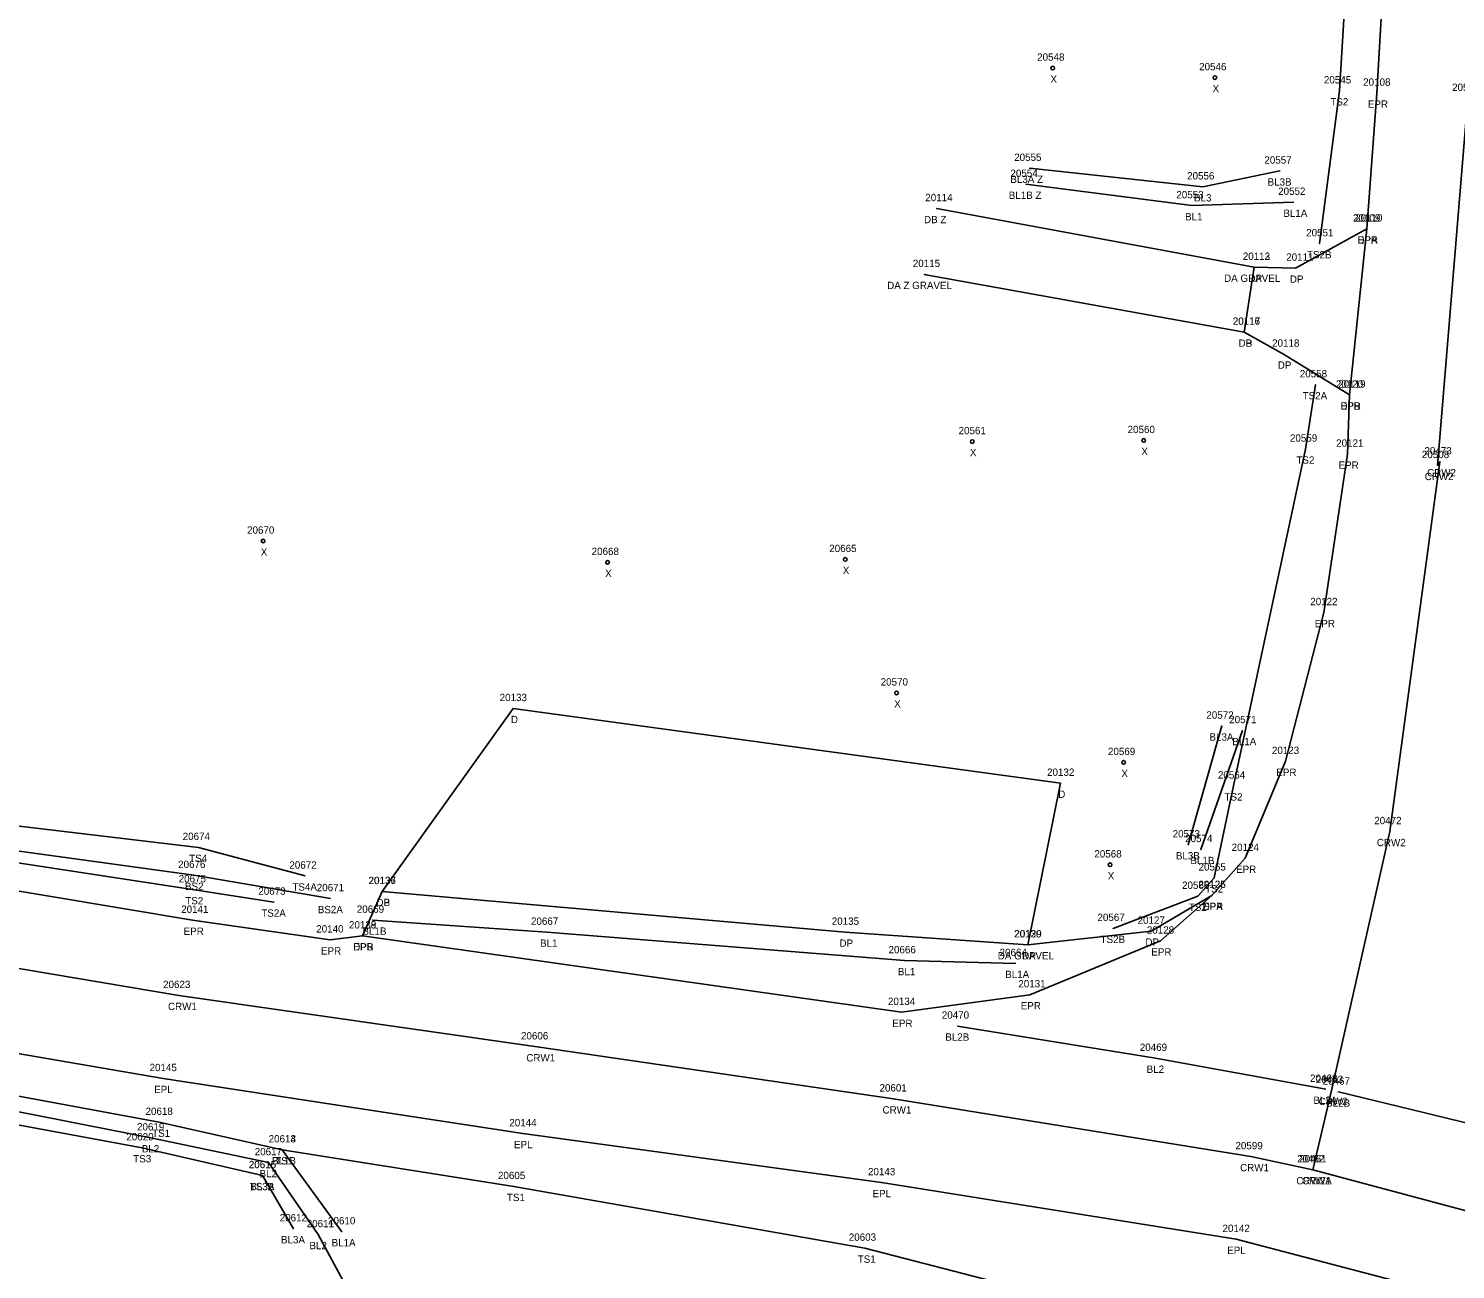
# Model space of a CAD drawing. Extents: x 1813127 to 1814107, y 1178171 to 1179078.
# Drawn here: x 1813477.1 to 1813671.6, y 1178740.3 to 1178909.4 of the extents above; entities that cross this region are included whole.
import ezdxf

# ---------------------------------------------------------------- set-up
doc = ezdxf.new("R2010")
doc.units = 0
for name, color, linetype in [('RD_DTM_BkLn1', 7, 'Continuous'), ('RD_DTM_BkLn2', 7, 'Continuous'), ('RD_EX_Driveway', 7, 'Continuous'), ('RD_EX_Driveway_txCode', 7, 'Continuous'), ('RD_EX_Road', 7, 'Continuous'), ('RD_EX_Road_txCode', 7, 'Continuous'), ('RD_SMD_Locator', 7, 'Continuous'), ('RD_SMD_Misc', 7, 'Continuous')]:
    doc.layers.add(name, color=color, linetype=linetype)

msp = doc.modelspace()

# ---------------------------------------------------------------- linework, layer by layer
at = {"layer": 'RD_DTM_BkLn1'}
for p, q in [((1813639.78, 1178814.35), (1813635.19, 1178798.15)), ((1813642.61, 1178813.73), (1813636.89, 1178797.51)), ((1813519.83, 1178745.4), (1813511.7, 1178756.57)), ((1813513.21, 1178745.81), (1813509.01, 1178753.06))]:
    msp.add_line(p, q, dxfattribs=at)
for points in [[(1813652.18, 1178753.85), (1813654.73, 1178764.67), (1813662.67, 1178799.96), (1813669.51, 1178850.38), (1813669.19, 1178849.87), (1813673.32, 1178899.93), (1813676.21, 1178946.85), (1813678.62, 1178996.65), (1813680.77, 1179045.99)], [(1813613.59, 1178890.39), (1813637.19, 1178887.86), (1813647.69, 1178890.02)], [(1813649.57, 1178885.76), (1813635.69, 1178885.29), (1813613.07, 1178888.21)], [(1813740.76, 1178717.86), (1813693.97, 1178742.65), (1813652.18, 1178753.85), (1813643.74, 1178755.64), (1813595, 1178763.51), (1813546.44, 1178770.61), (1813497.6, 1178777.62), (1813448.59, 1178785.89), (1813401.09, 1178795.04), (1813353.48, 1178806.76), (1813306.05, 1178819.85), (1813260.03, 1178834.12), (1813213.64, 1178849.47), (1813166.61, 1178866.29)], [(1813611.65, 1178781.98), (1813596.53, 1178782.36), (1813547.76, 1178786.24), (1813524.02, 1178787.88)], [(1813653.94, 1178764.83), (1813630.73, 1178769.05), (1813603.76, 1178773.44)], [(1813521.54, 1178735.83), (1813516.61, 1178745.01), (1813509.8, 1178754.82), (1813493.76, 1178758.2), (1813445.29, 1178767.72), (1813423.54, 1178771.64)], [(1813708.13, 1178748.38), (1813678.84, 1178758.82), (1813655.66, 1178764.45)]]:
    msp.add_lwpolyline(points, dxfattribs=at)
at = {"layer": 'RD_DTM_BkLn2'}
for points in [[(1813665.28, 1179045.88), (1813659.72, 1178996.23), (1813658.69, 1178948.21), (1813655.81, 1178900.95), (1813653.1, 1178880.11)], [(1813652.52, 1178860.88), (1813651.18, 1178852.11), (1813641.38, 1178806.18), (1813638.75, 1178793.64), (1813636.51, 1178791.14), (1813624.96, 1178786.76)], [(1813510.57, 1178790.34), (1813499.73, 1178792.03), (1813450.92, 1178799.48), (1813417.46, 1178804.73), (1813418, 1178808.5)], [(1813514.81, 1178793.9), (1813500.27, 1178797.8), (1813451.77, 1178803.56), (1813418, 1178808.5)], [(1813518.26, 1178790.82), (1813499.66, 1178793.99), (1813451.03, 1178800.68), (1813418.59, 1178806.73)], [(1813728.98, 1178703.48), (1813680.74, 1178720.54), (1813670.9, 1178725.8), (1813665.35, 1178733.78), (1813654.36, 1178734.63), (1813647.32, 1178729.73), (1813639.1, 1178730.74), (1813591.11, 1178743.16), (1813543.28, 1178751.57), (1813511.7, 1178756.57), (1813494.92, 1178760.32), (1813445.74, 1178769.42), (1813422.91, 1178772.94), (1813422.78, 1178770.34)], [(1813509.01, 1178753.06), (1813492.62, 1178756.85), (1813444.34, 1178765.75), (1813422.78, 1178770.34)]]:
    msp.add_lwpolyline(points, dxfattribs=at)
at = {"layer": 'RD_EX_Driveway'}
for p, q in [((1813644.18, 1178876.9), (1813600.91, 1178884.9)), ((1813599.2, 1178875.92), (1813642.83, 1178868.05))]:
    msp.add_line(p, q, dxfattribs=at)
for points in [[(1813659.53, 1178882.12), (1813649.82, 1178876.78), (1813644.18, 1178876.9), (1813642.83, 1178868.05), (1813648.18, 1178865.06), (1813657.19, 1178859.48)], [(1813613.34, 1178784.52), (1813617.78, 1178806.55), (1813543.17, 1178816.74), (1813525.31, 1178791.79)], [(1813638.42, 1178791.25), (1813630.13, 1178786.38), (1813613.34, 1178784.52), (1813588.43, 1178786.24), (1813525.31, 1178791.79), (1813522.62, 1178785.74)]]:
    msp.add_lwpolyline(points, dxfattribs=at)
at = {"layer": 'RD_EX_Road'}
for points in [[(1813668.47, 1179045.78), (1813666.19, 1178996.77), (1813663.63, 1178947.81), (1813660.91, 1178900.64), (1813659.53, 1178882.12), (1813657.19, 1178859.48), (1813656.91, 1178851.42), (1813653.67, 1178829.82), (1813648.43, 1178809.53), (1813642.94, 1178796.31), (1813638.42, 1178791.25), (1813631.39, 1178785.04), (1813613.59, 1178777.71), (1813596.09, 1178775.31), (1813522.62, 1178785.74), (1813518.21, 1178785.19), (1813499.47, 1178787.87), (1813450.56, 1178796.06)], [(1813732.94, 1178707.95), (1813689.88, 1178731.75), (1813641.71, 1178744.36), (1813593.37, 1178752.09), (1813544.49, 1178758.77), (1813495.45, 1178766.29), (1813446.8, 1178774.66), (1813426.54, 1178777.95), (1813403.21, 1178782.55), (1813398.65, 1178783.84), (1813350.68, 1178796.09), (1813343.23, 1178797.92), (1813318.7, 1178804.23), (1813303.26, 1178808.85), (1813256.8, 1178823.17), (1813209.81, 1178838.91), (1813163.27, 1178855.57)]]:
    msp.add_lwpolyline(points, dxfattribs=at)
at = {"layer": 'RD_SMD_Locator'}
for centre, radius in [((1813616.72, 1178904.05), 0.25), ((1813638.82, 1178902.75), 0.25), ((1813655.81, 1178900.95), 0.001), ((1813660.91, 1178900.64), 0.001), ((1813613.59, 1178890.39), 0.001), ((1813647.69, 1178890.02), 0.001), ((1813613.07, 1178888.21), 0.001), ((1813637.19, 1178887.86), 0.001), ((1813649.57, 1178885.76), 0.001), ((1813600.91, 1178884.9), 0.001), ((1813635.69, 1178885.29), 0.001), ((1813659.53, 1178882.12), 0.001), ((1813659.53, 1178882.12), 0.001), ((1813653.1, 1178880.11), 0.001), ((1813599.2, 1178875.92), 0.001), ((1813644.18, 1178876.9), 0.001), ((1813644.18, 1178876.9), 0.001), ((1813649.82, 1178876.78), 0.001), ((1813642.83, 1178868.05), 0.001), ((1813642.83, 1178868.05), 0.001), ((1813648.18, 1178865.06), 0.001), ((1813652.52, 1178860.88), 0.001), ((1813657.19, 1178859.48), 0.001), ((1813657.19, 1178859.48), 0.001), ((1813605.75, 1178853.13), 0.25), ((1813629.12, 1178853.28), 0.25), ((1813651.18, 1178852.11), 0.001), ((1813656.91, 1178851.42), 0.001), ((1813669.19, 1178849.87), 0.001), ((1813669.51, 1178850.38), 0.001), ((1813509.08, 1178839.57), 0.25), ((1813556.04, 1178836.66), 0.25), ((1813588.43, 1178837.06), 0.25), ((1813653.67, 1178829.82), 0.001), ((1813595.43, 1178818.86), 0.25), ((1813543.17, 1178816.74), 0.001), ((1813639.78, 1178814.35), 0.001), ((1813642.61, 1178813.73), 0.001), ((1813626.39, 1178809.38), 0.25), ((1813648.43, 1178809.53), 0.001), ((1813617.78, 1178806.55), 0.001), ((1813641.38, 1178806.18), 0.001), ((1813662.67, 1178799.96), 0.001), ((1813635.19, 1178798.15), 0.001), ((1813500.27, 1178797.8), 0.001), ((1813636.89, 1178797.51), 0.001), ((1813642.94, 1178796.31), 0.001), ((1813624.54, 1178795.42), 0.25), ((1813499.66, 1178793.99), 0.001), ((1813514.81, 1178793.9), 0.001), ((1813638.75, 1178793.64), 0.001), ((1813499.73, 1178792.03), 0.001), ((1813510.57, 1178790.34), 0.001), ((1813518.26, 1178790.82), 0.001), ((1813525.31, 1178791.79), 0.001), ((1813525.31, 1178791.79), 0.001), ((1813636.51, 1178791.14), 0.001), ((1813638.42, 1178791.25), 0.001), ((1813638.42, 1178791.25), 0.001), ((1813499.47, 1178787.87), 0.001), ((1813524.02, 1178787.88), 0.001), ((1813547.76, 1178786.24), 0.001), ((1813588.43, 1178786.24), 0.001), ((1813624.96, 1178786.76), 0.001), ((1813630.13, 1178786.38), 0.001), ((1813518.21, 1178785.19), 0.001), ((1813522.62, 1178785.74), 0.001), ((1813522.62, 1178785.74), 0.001), ((1813613.34, 1178784.52), 0.001), ((1813613.34, 1178784.52), 0.001), ((1813631.39, 1178785.04), 0.001), ((1813596.53, 1178782.36), 0.001), ((1813611.65, 1178781.98), 0.001), ((1813497.6, 1178777.62), 0.001), ((1813613.59, 1178777.71), 0.001), ((1813596.09, 1178775.31), 0.001), ((1813603.76, 1178773.44), 0.001), ((1813546.44, 1178770.61), 0.001), ((1813630.73, 1178769.05), 0.001), ((1813495.45, 1178766.29), 0.001), ((1813653.94, 1178764.83), 0.001), ((1813595, 1178763.51), 0.001), ((1813654.73, 1178764.67), 0.001), ((1813655.66, 1178764.45), 0.001), ((1813494.92, 1178760.32), 0.001), ((1813493.76, 1178758.2), 0.001), ((1813544.49, 1178758.77), 0.001), ((1813492.62, 1178756.85), 0.001), ((1813511.7, 1178756.57), 0.001), ((1813511.7, 1178756.57), 0.001), ((1813643.74, 1178755.64), 0.001), ((1813509.8, 1178754.82), 0.001), ((1813652.18, 1178753.85), 0.001), ((1813652.18, 1178753.85), 0.001), ((1813509.01, 1178753.06), 0.001), ((1813509.01, 1178753.06), 0.001), ((1813543.28, 1178751.57), 0.001), ((1813593.37, 1178752.09), 0.001), ((1813513.21, 1178745.81), 0.001), ((1813519.83, 1178745.4), 0.001), ((1813516.61, 1178745.01), 0.001), ((1813641.71, 1178744.36), 0.001), ((1813591.11, 1178743.16), 0.001)]:
    msp.add_circle(centre, radius, dxfattribs=at)

# ---------------------------------------------------------------- texts
at = {"layer": 'RD_EX_Driveway_txCode'}
for s, p in [('20114', (1813599.35, 1178885.9)), ('DB Z', (1813599.18, 1178882.9)), ('20110', (1813657.94, 1178883.12)), ('DPA', (1813658.26, 1178880.12)), ('20115', (1813597.65, 1178876.92)), ('20112', (1813642.63, 1178877.9)), ('20113', (1813642.63, 1178877.9)), ('20111', (1813648.55, 1178877.78)), ('DA GRAVEL', (1813640.08, 1178874.9)), ('DP', (1813643.4, 1178874.9)), ('DP', (1813649.04, 1178874.78)), ('DA Z GRAVEL', (1813594.15, 1178873.92)), ('20116', (1813641.26, 1178869.05)), ('20117', (1813641.28, 1178869.05)), ('DB', (1813642.05, 1178866.05)), ('DP', (1813642.05, 1178866.05)), ('20118', (1813646.63, 1178866.06)), ('DP', (1813647.4, 1178863.06)), ('20119', (1813655.64, 1178860.48)), ('DPB', (1813655.94, 1178857.48)), ('20133', (1813541.33, 1178817.74)), ('D', (1813542.86, 1178814.74)), ('20132', (1813615.95, 1178807.55)), ('D', (1813617.47, 1178804.55)), ('20136', (1813523.45, 1178792.79)), ('20137', (1813523.48, 1178792.79)), ('20126', (1813636.57, 1178792.25)), ('DP', (1813524.53, 1178789.79)), ('DB', (1813524.53, 1178789.79)), ('DPA', (1813637.16, 1178789.25)), ('20135', (1813586.6, 1178787.24)), ('20127', (1813628.29, 1178787.38)), ('20138', (1813520.79, 1178786.74)), ('20130', (1813611.46, 1178785.52)), ('20129', (1813611.5, 1178785.52)), ('DPB', (1813521.37, 1178783.74)), ('DP', (1813587.65, 1178784.24)), ('DP', (1813629.35, 1178784.38)), ('DA GRAVEL', (1813609.23, 1178782.52)), ('DP', (1813612.56, 1178782.52))]:
    msp.add_text(s, height=1, dxfattribs=at).set_placement(p)
at = {"layer": 'RD_EX_Road_txCode'}
for s, p in [('20108', (1813659.04, 1178901.64)), ('EPR', (1813659.68, 1178898.64)), ('20109', (1813657.66, 1178883.12)), ('EPR', (1813658.3, 1178880.12)), ('20120', (1813655.32, 1178860.48)), ('EPR', (1813655.96, 1178857.48)), ('20121', (1813655.36, 1178852.42)), ('EPR', (1813655.68, 1178849.42)), ('20122', (1813651.83, 1178830.82)), ('EPR', (1813652.44, 1178827.82)), ('20123', (1813646.6, 1178810.53)), ('EPR', (1813647.2, 1178807.53)), ('20124', (1813641.11, 1178797.31)), ('EPR', (1813641.71, 1178794.31)), ('20125', (1813636.59, 1178792.25)), ('EPR', (1813637.2, 1178789.25)), ('20141', (1813497.92, 1178788.87)), ('EPR', (1813498.25, 1178785.87)), ('20140', (1813516.33, 1178786.19)), ('20139', (1813520.79, 1178786.74)), ('20128', (1813629.55, 1178786.04)), ('EPR', (1813521.39, 1178783.74)), ('EPR', (1813516.98, 1178783.19)), ('EPR', (1813630.16, 1178783.04)), ('20131', (1813612.03, 1178778.71)), ('20134', (1813594.26, 1178776.31)), ('EPR', (1813612.36, 1178775.71)), ('EPR', (1813594.86, 1178773.31)), ('20145', (1813493.61, 1178767.29)), ('EPL', (1813494.24, 1178764.29)), ('20144', (1813542.65, 1178759.77)), ('EPL', (1813543.28, 1178756.77)), ('20143', (1813591.54, 1178753.09)), ('EPL', (1813592.16, 1178750.09)), ('20142', (1813639.87, 1178745.36)), ('EPL', (1813640.5, 1178742.36))]:
    msp.add_text(s, height=1, dxfattribs=at).set_placement(p)
at = {"layer": 'RD_SMD_Misc'}
for s, p in [('20548', (1813614.6, 1178905.05)), ('X', (1813616.41, 1178902.05)), ('20546', (1813636.68, 1178903.75)), ('20545', (1813653.69, 1178901.95)), ('X', (1813638.51, 1178900.75)), ('20509', (1813671.16, 1178900.93)), ('TS2', (1813654.56, 1178898.95)), ('20555', (1813611.47, 1178891.39)), ('20557', (1813645.57, 1178891.02)), ('20554', (1813610.96, 1178889.21)), ('BL3A Z', (1813610.94, 1178888.39)), ('20556', (1813635.04, 1178888.86)), ('BL3B', (1813646.01, 1178888.02)), ('20552', (1813647.45, 1178886.76)), ('BL1B Z', (1813610.73, 1178886.21)), ('20553', (1813633.57, 1178886.29)), ('BL3', (1813635.98, 1178885.86)), ('BL1', (1813634.76, 1178883.29)), ('BL1A', (1813648.16, 1178883.76)), ('20551', (1813651.27, 1178881.11)), ('TS2B', (1813651.38, 1178878.11)), ('20558', (1813650.4, 1178861.88)), ('TS2A', (1813650.79, 1178858.88)), ('20561', (1813603.89, 1178854.13)), ('20560', (1813626.93, 1178854.28)), ('20559', (1813649.06, 1178853.11)), ('20473', (1813667.39, 1178851.38)), ('X', (1813605.43, 1178851.13)), ('X', (1813628.8, 1178851.28)), ('TS2', (1813649.94, 1178850.11)), ('20508', (1813667.04, 1178850.87)), ('CRW2', (1813667.43, 1178847.87)), ('CRW2', (1813667.75, 1178848.38)), ('20670', (1813506.9, 1178840.57)), ('20665', (1813586.26, 1178838.06)), ('X', (1813508.77, 1178837.57)), ('20668', (1813553.87, 1178837.66)), ('X', (1813555.72, 1178834.66)), ('X', (1813588.11, 1178835.06)), ('20570', (1813593.27, 1178819.86)), ('X', (1813595.11, 1178816.86)), ('20572', (1813637.66, 1178815.35)), ('20571', (1813640.78, 1178814.73)), ('BL3A', (1813638.09, 1178812.35)), ('BL1A', (1813641.2, 1178811.73)), ('20569', (1813624.25, 1178810.38)), ('X', (1813626.08, 1178807.38)), ('20564', (1813639.24, 1178807.18)), ('TS2', (1813640.14, 1178804.18)), ('20472', (1813660.55, 1178800.96)), ('20573', (1813633.07, 1178799.15)), ('20674', (1813498.12, 1178798.8)), ('20574', (1813634.77, 1178798.51)), ('CRW2', (1813660.9, 1178797.96)), ('20676', (1813497.5, 1178794.99)), ('TS4', (1813499.02, 1178795.8)), ('20568', (1813622.4, 1178796.42)), ('BL3B', (1813633.51, 1178796.15)), ('BL1B', (1813635.49, 1178795.51)), ('20675', (1813497.58, 1178793.03)), ('20672', (1813512.67, 1178794.9)), ('X', (1813624.22, 1178793.42)), ('20565', (1813636.6, 1178794.64)), ('BS2', (1813498.43, 1178791.99)), ('20673', (1813508.43, 1178791.34)), ('TS4A', (1813513.08, 1178791.9)), ('20671', (1813516.4, 1178791.82)), ('20566', (1813634.35, 1178792.14)), ('TS2', (1813637.5, 1178791.64)), ('TS2', (1813498.48, 1178790.03)), ('TS2', (1813635.27, 1178789.14)), ('TS2A', (1813508.84, 1178788.34)), ('BS2A', (1813516.54, 1178788.82)), ('20669', (1813521.86, 1178788.88)), ('20667', (1813545.6, 1178787.24)), ('20567', (1813622.82, 1178787.76)), ('BL1B', (1813522.63, 1178785.88)), ('BL1', (1813546.84, 1178784.24)), ('20666', (1813594.34, 1178783.36)), ('TS2B', (1813623.24, 1178784.76)), ('20664', (1813609.48, 1178782.98)), ('BL1', (1813595.61, 1178780.36)), ('BL1A', (1813610.24, 1178779.98)), ('20623', (1813495.45, 1178778.62)), ('CRW1', (1813496.12, 1178775.62)), ('20470', (1813601.6, 1178774.44)), ('20606', (1813544.24, 1178771.61)), ('BL2B', (1813602.08, 1178771.44)), ('20469', (1813628.59, 1178770.05)), ('CRW1', (1813544.96, 1178768.61)), ('BL2', (1813629.52, 1178767.05)), ('20468', (1813651.8, 1178765.83)), ('20601', (1813593.11, 1178764.51)), ('20463', (1813652.59, 1178765.67)), ('20467', (1813653.52, 1178765.45)), ('BL2A', (1813652.25, 1178762.83)), ('CRW2', (1813652.97, 1178762.67)), ('BL2B', (1813653.99, 1178762.45)), ('20618', (1813493.06, 1178761.32)), ('CRW1', (1813593.52, 1178761.51)), ('20619', (1813491.9, 1178759.2)), ('TS1', (1813493.96, 1178758.32)), ('20620', (1813490.44, 1178757.85)), ('BL2', (1813492.55, 1178756.2)), ('20613', (1813509.84, 1178757.57)), ('20614', (1813509.84, 1178757.57)), ('20599', (1813641.63, 1178756.64)), ('TS3', (1813491.38, 1178754.85)), ('20617', (1813507.94, 1178755.82)), ('BL1B', (1813510.3, 1178754.57)), ('TS1', (1813510.73, 1178754.57)), ('20462', (1813650.04, 1178754.85)), ('20461', (1813650.32, 1178754.85)), ('20616', (1813507.13, 1178754.06)), ('20615', (1813507.15, 1178754.06)), ('BL2', (1813508.6, 1178752.82)), ('20605', (1813541.1, 1178752.57)), ('CRW1', (1813642.26, 1178753.64)), ('TS3A', (1813507.28, 1178751.06)), ('BL3B', (1813507.33, 1178751.06)), ('CRW2A', (1813649.93, 1178751.85)), ('CRW1', (1813650.7, 1178751.85)), ('TS1', (1813542.32, 1178749.57)), ('20612', (1813511.35, 1178746.81)), ('20610', (1813517.94, 1178746.4)), ('20611', (1813515.03, 1178746.01)), ('BL3A', (1813511.52, 1178743.81)), ('BL2', (1813515.4, 1178743.01)), ('BL1A', (1813518.42, 1178743.4)), ('20603', (1813588.92, 1178744.16)), ('TS1', (1813590.14, 1178741.16))]:
    msp.add_text(s, height=1, dxfattribs=at).set_placement(p)

doc.saveas('drawing.dxf')
